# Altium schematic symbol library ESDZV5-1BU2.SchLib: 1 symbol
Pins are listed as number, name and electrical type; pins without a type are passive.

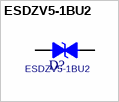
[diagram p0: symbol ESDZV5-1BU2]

## ESDZV5-1BU2
designator D?
footprint ST_ST0201B_a
pins: 1, 2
